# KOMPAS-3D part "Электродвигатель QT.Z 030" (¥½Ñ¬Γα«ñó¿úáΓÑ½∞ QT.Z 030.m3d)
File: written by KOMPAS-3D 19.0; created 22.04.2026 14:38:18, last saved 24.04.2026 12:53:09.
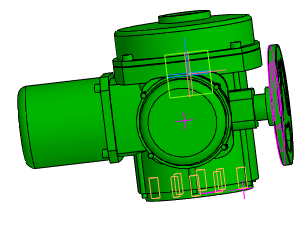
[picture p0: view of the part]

Document properties: Автор: Энергия; Полное имя файла: Z:\3.Личные\kachalov\3d для проектировщиков\1.7 Тип 023F.Z Затвор дисковый поворотный фланцевый с двумя эксцентриками\Привод\Электродвигатель QT.Z 030.m3d

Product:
- Part/product: Электродвигатель QT.Z 030
    Масса: 43.1664

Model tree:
1. Эскиз:1
2. Элемент вращения:1
     Угол 1 = 360
3. Эскиз:2  (with: Элемент вращения:1)
4. Элемент выдавливания:1  (with: Элемент вращения:1)
5. Эскиз:3  (with: Элемент вращения:1)
6. Элемент выдавливания:2
     Расстояние 1 = 130
7. Эскиз:4  (with: Элемент выдавливания:2)
8. Элемент выдавливания:3
     Расстояние 1 = 10
9. Эскиз:5  (with: Элемент выдавливания:2, Элемент выдавливания:3)
10. Элемент выдавливания:4  (with: Элемент вращения:1)
     Расстояние 1 = -130
11. Массив по концентрической сетке:1  (with: Элемент выдавливания:4, Эскиз:5, Элемент выдавливания:2)  (6 pattern instances)
     Шаг 2 = 360
12. Эскиз:6  (with: Элемент выдавливания:1)
13. Элемент выдавливания:5
     Расстояние 1 = 90
14. Эскиз:7  (with: Элемент выдавливания:5)
15. Элемент выдавливания:6
     Расстояние 1 = 10
16. Эскиз:9  (with: Элемент выдавливания:6)
17. Элемент вращения:3
     Угол 1 = 360
18. Эскиз:10  (with: Элемент выдавливания:1)
19. Элемент выдавливания:8
     Расстояние 1 = 90
20. Эскиз:11  (with: Элемент выдавливания:8)
21. Элемент выдавливания:9
     Расстояние 1 = 8
22. Эскиз:12  (with: Элемент выдавливания:9)
23. Элемент выдавливания:10
     Расстояние 1 = 44
24. Эскиз:19  (with: Элемент выдавливания:10)
25. Эскиз:20  (with: Элемент выдавливания:10)
26. Элемент выдавливания:14
     Расстояние 1 = 10
27. Эскиз:21  (with: Элемент выдавливания:14)
28. Элемент выдавливания:15
     Расстояние 1 = 25
29. Скругление:3  (with: Элемент выдавливания:15)
     Радиус = 10
30. Эскиз:22  (with: Элемент вращения:1)
31. Скругление:4  (with: Элемент выдавливания:10, Элемент выдавливания:14, Элемент выдавливания:15)
     Радиус = 2
32. Эскиз:23  (with: Элемент вращения:1)
33. Элемент выдавливания:16
     Расстояние 1 = 8
34. Эскиз:24  (with: Элемент выдавливания:16)
35. Элемент выдавливания:17
     Расстояние 2 = 2
36. Эскиз:25
37. Элемент выдавливания:19
     Расстояние 1 = 75
38. Эскиз:26  (with: Элемент выдавливания:19)
39. Элемент выдавливания:20
     Расстояние 1 = 15
40. Эскиз:27  (with: Элемент выдавливания:20)
41. Элемент выдавливания:21
     Расстояние 1 = 10
42. Эскиз:28  (with: Элемент выдавливания:21)
43. Элемент выдавливания:22
     Расстояние 1 = 10
44. Эскиз:29  (with: Элемент выдавливания:3)
45. Эскиз:30  (with: Элемент выдавливания:3)
46. Элемент выдавливания:23
     Расстояние 2 = 90
47. Эскиз:31  (with: Элемент выдавливания:3)
48. Элемент выдавливания:24
     Расстояние 2 = 2
49. Эскиз:32  (with: Элемент выдавливания:6)
50. Элемент выдавливания:25
     Расстояние 1 = 7
51. Эскиз:33  (with: Элемент вращения:1)
52. Элемент выдавливания:26
     Расстояние 1 = 7
53. Эскиз:34  (with: Элемент выдавливания:14)
54. Элемент выдавливания:27
     Расстояние 1 = 5
55. Скругление:6  (with: Элемент выдавливания:22)
     Радиус = 1
56. Эскиз:35  (with: Элемент выдавливания:2, Элемент выдавливания:4)
57. Элемент выдавливания:28
     Расстояние 1 = 5
58. Скругление:7  (with: Элемент вращения:1)
     Радиус = 5
59. Эскиз:36  (with: Элемент вращения:1)
60. Отверстие:3  (with: Элемент выдавливания:3)  (labels: M10)
     Глубина выреза = 30; Диаметр отверстия = 8.3762; Угол конуса дна = 118; Расстояние 1 = 46; Расстояние 2 = -8; Диаметр зенковки = 12; Глубина зенковки = 1.8119; Угол зенковки = 90
61. M10  (labels: cil0_24705-2004 coarse)
     Длина резьбы = 25; Шаг резьбы = 1.5; Номинальный диаметр резьбы = 10
62. Отверстие:4  (with: Элемент выдавливания:3)  (labels: M8)
     Глубина выреза = 30; Диаметр отверстия = 6.64684; Угол конуса дна = 118; Расстояние 1 = 19.7487; Расстояние 2 = -32.7487; Диаметр зенковки = 10; Глубина зенковки = 1.67658; Угол зенковки = 90
63. M8  (labels: cil0_24705-2004 coarse)
     Длина резьбы = 25; Шаг резьбы = 1.25; Номинальный диаметр резьбы = 8
64. Массив по концентрической сетке:4  (with: Отверстие:3, Эскиз:29)  (labels: M10)  (2 pattern instances)
65. Отверстие:3  (with: Эскиз:29)  (labels: M10)
66. Отверстие:3  (with: Эскиз:29)  (labels: M10)
67. Массив по концентрической сетке:5  (with: Отверстие:4, Эскиз:29)  (labels: M8)  (2 pattern instances)
68. Отверстие:4  (with: Эскиз:29)  (labels: M8)
69. Отверстие:4  (with: Эскиз:29)  (labels: M8)

Expressions: 360/4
